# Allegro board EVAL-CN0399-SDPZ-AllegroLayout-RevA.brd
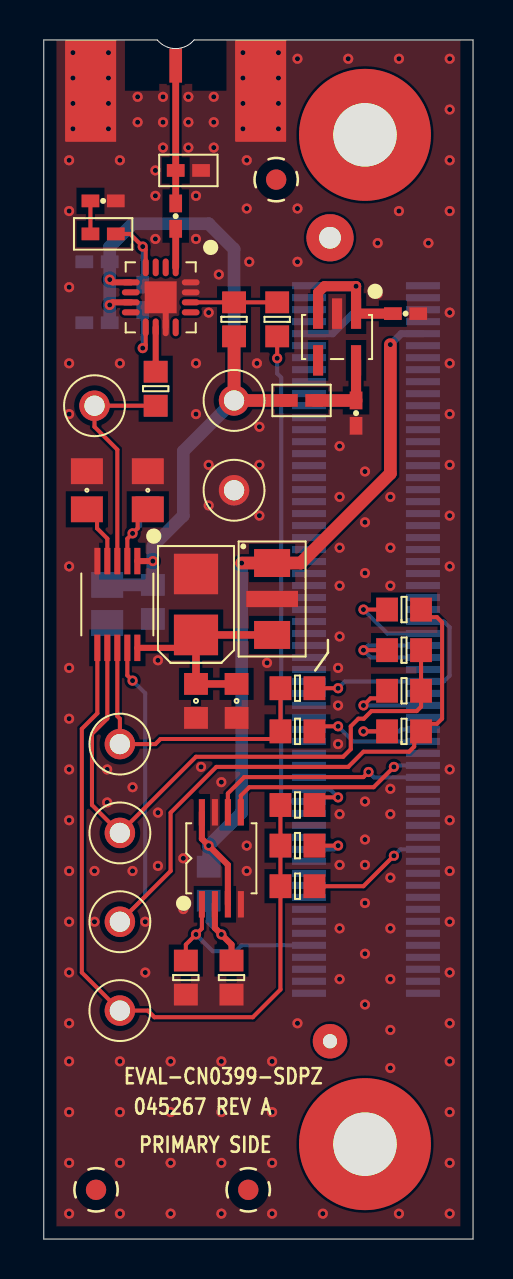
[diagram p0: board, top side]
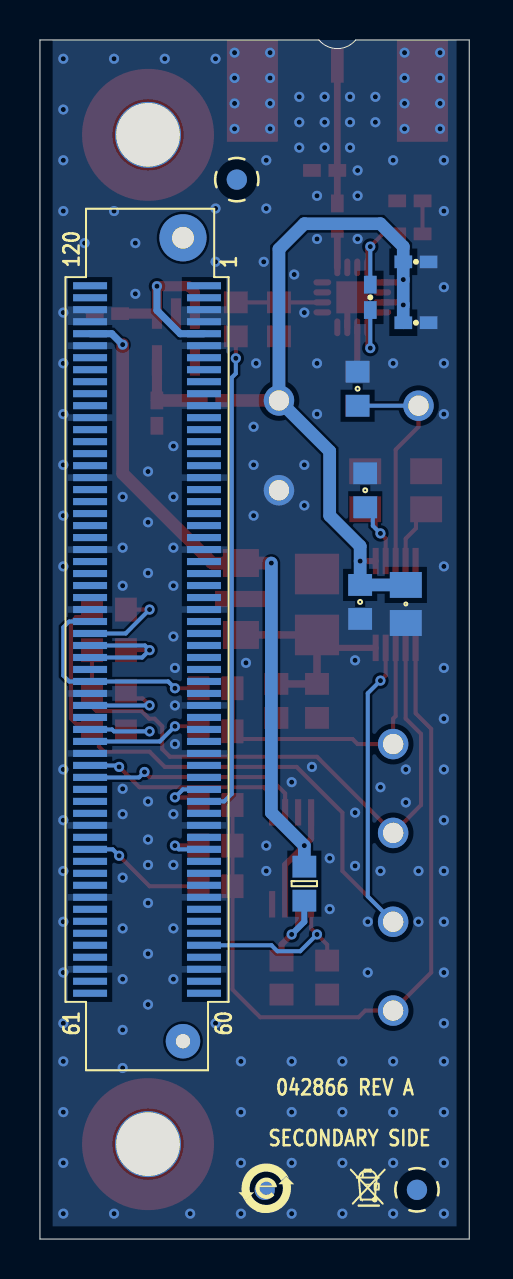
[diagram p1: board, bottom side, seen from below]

Outline 21.49 x 59.99 mm; copper layers: TOP, L2_GND, L3_GND, BOTTOM. Coordinates in mm from the lower left corner of the outline.
Outline path: 5.68,59.99 0,59.99 0,0 21.49,0 21.49,59.99 7.52,59.99

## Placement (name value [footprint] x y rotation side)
C1  1uF  [C0402]  18.11 46.3 0 top
C2  0.1UF  [C0402]  2.97 51.94 0 top
C3  1uF  [C0402]  15.63 41.32 270 top
C4  0.47uF  [C0402]  6.6 51.18 270 top
C5  0.1UF  [C0402]  4.95 47.12 270 bottom
C6  100PF  [C0402]  2.67 48.9 180 bottom
C7  0.1UF  [C0402]  2.67 45.85 180 bottom
C8  TBD0603  [C0603]  5.59 42.55 90 bottom
C10  10uF  [C3528]  7.62 31.75 90 top
C11  1uF  [C0805]  2.16 37.47 90 top
C12  0.1uF  [C0603]  9.65 26.92 270 top
C13  0.1uF  [C0603]  7.62 26.92 270 top
C14  0.1uF  [C0603]  5.21 37.47 90 bottom
C15  1uF  [C0805]  5.21 37.47 90 top
C16  1uF  [C0805]  3.18 31.78 270 bottom
C17  0.1uF  [C0603]  5.46 31.88 270 bottom
CONSTB  5001  [CNKEY5001TP]  3.81 11.43 0 top
CSB  5001  [CNKEY5001TP]  3.81 20.32 0 top
FL1  1000pF  [FLSML126W71H87]  11.43 32.02 270 top
NOREF  -  []  -144.78 23.77 0 top
NOREF#2  -  []  16.08 4.75 0 top
NOREF#3  -  [unnamed#2]  10.24 2.46 0 top
NOREF#4  -  []  6.53 59.57 0 top
NOREF#5  -  []  -166.45 262.33 0 top
NOREF#6  -  []  -263.14 5.03 0 top
NOREF#7  -  []  -188.06 -103.86 0 top
NOREF#8  -  [unnamed#2]  2.62 2.46 0 top
NOREF#9  -  []  6.6 60.76 0 top
NOREF#10  -  []  0 59.99 270 top
NOREF#11  -  []  0 0.05 0 top
NOREF#12  -  [unnamed#2]  11.63 53.01 0 top
NOREF#13  -  []  21.49 0 90 top
NOREF#14  -  []  21.49 59.99 180 top
NOREF#15  -  []  0 59.99 0 top
NOREF#16  -  []  -188.06 -103.86 0 top
NOREF#17  -  []  0 0 0 top
NOREF#18  -  []  -188.91 -27.62 0 top
NOREF#19  -  []  0 0 0 top
NOREF#20  -  []  6.59 59.56 0 top
NOREF#21  -  []  -414.4 -247.14 0 top
NOREF#22  -  []  16.08 4.75 0 top
NOREF#23  -  []  21.49 0 90 top
NOREF#24  -  []  10.16 2.54 180 bottom
NOREF#25  -  [unnamed#2]  11.63 53.01 180 bottom
NOREF#26  -  []  5.03 2.57 180 bottom
NOREF#27  -  [unnamed#2]  2.62 2.46 180 bottom
NOREF#28  -  [unnamed#2]  10.24 2.46 180 bottom
P1  FX8-120S-SV(21)  [CNHRSFX8-120S-SV_A]  16.13 30 270 bottom
R1  0  [R0603]  12.7 19.68 0 top
R2  0  [R0603]  12.7 21.72 0 top
R3  TBD0603  [R0603]  12.7 17.65 180 top
R4  100K  [R0603]  7.11 13.08 270 top
R5  0  [R0603]  12.7 25.4 180 top
R6  0  [R0603]  18.03 25.4 0 top
R7  0  [R0603]  18.03 27.43 0 top
R8  0  [R0603]  12.7 27.56 180 top
R9  0  [R0603]  18.03 29.46 0 top
R10  0  [R0603]  18.03 31.5 0 top
R11  TBD0603  [R0603]  8.26 17.78 270 bottom
R12  100K  [R0603]  9.4 13.08 270 top
R13  4.02  [R0402]  2.97 50.29 180 top
R14  82.5  [R0402]  7.24 53.47 0 top
R15  0  [R0402]  12.9 41.96 180 top
R16  0  [R0603]  11.68 46.02 90 top
R17  0  [R0603]  9.53 46.02 270 top
R18  0  [R0603]  5.6 42.55 270 top
RFIN  142-0801-811  [CNSMAL686W375H161]  6.6 57.63 90 top
SCLK  5001  [CNKEY5001TP]  3.81 24.77 0 top
SDO  5001  [CNKEY5001TP]  3.81 15.88 0 top
TPGND  20-2137  [CNKEY5001TP]  9.53 37.47 0 top
TPVPOS  20-313137  [CNKEY5001TP]  9.53 41.96 0 top
U1  ADL5904ACPZ  [QFN16_3X3_PAD1_6X1_6]  5.85 47.12 180 top
U2  24LC32A-I/MS  [MSOP8]  8.89 19.05 0 top
U3  ADP160AUJZ-3.3  [TSOT-5]  14.68 45.13 180 top
U4  AD7091RBRMZ  [RM10]  3.68 31.75 180 top
VRMS  5001  [CNKEY5001TP]  2.54 41.69 0 top

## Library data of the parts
C1 C3 = CAP: Tolerance: 10; User Part Number: UPN; part number: CAP_SM-1UF,16V,10,E020874,C0402; tolerance: 10
C2 C5 C7 = CAP: Tolerance: 10; User Part Number: UPN; part number: CAP_SM-0.1UF,16V,10,E007200,C0402; tolerance: 10
C4 = CAP: Tolerance: 10; User Part Number: UPN; part number: CAP_SM-0.47UF,16V,10,E016653,C0402; tolerance: 10
C6 = CAP: Tolerance: 5; User Part Number: UPN; part number: CAP_SM-100PF,50V,5,E023843,C0402; tolerance: 5
C8 = CAP: User Part Number: UPN; part number: CAP_SM-TBD0603,TBD0603,TBD0603,E000382,C0603
C10 = CAPP: User Part Number: UPN; Tolerance: 10; part number: CAPP_SM-10UF,20V,10,E011346,C3528; tolerance: 10
C11 C15 C16 = CAP: Tolerance: 10; User Part Number: UPN; part number: CAP_SM-1UF,100V,10,E014208,C0805; tolerance: 10
C12 C13 = CAP: Tolerance: 10; User Part Number: UPN; part number: CAP_SM-0.1UF,50V,10,E015248,C0603; tolerance: 10
C14 C17 = CAP: Tolerance: 10; User Part Number: UPN; part number: CAP_SM-0.1UF,50V,10,E011865,C0603; tolerance: 10
CONSTB CSB SCLK SDO VRMS = CNTP1P: User Part Number: UPN; alternate symbols: (CNBANANA_ALT); part number: CNTP1P_TH-5001,E005347,CNKEY5001TP
FL1 = FLTR3P_V3: User Part Number: UPN; part number: FLTR3P_V3_SM-1000PF,E019686,FLSML126W71H87
P1 = CN120P_V4: User Part Number: UPN; part number: CN120P_V4_SM-FX8-120S-SV(21),E016993,CNHRSFX8-120S-SV_A
R1 R2 R5-R10 R16 R17 = RES: Tolerance: 1; User Part Number: UPN; part number: RES_SM-0,E004207,1/16W,1,R0603; tolerance: 1
R3 R11 = RES: User Part Number: UPN; part number: RES_SM-TBD0603,E004050,TBD0603,TBD0603,R0603
R4 R12 = RES: Tolerance: 1; User Part Number: UPN; part number: RES_SM-100K,E018430,1/16W,1,R0603; tolerance: 1
R13 = RES: Tolerance: 1; User Part Number: UPN; part number: RES_SM-4.02,E016605,1/16W,1,R0402; tolerance: 1
R14 = RES: Tolerance: 1; User Part Number: UPN; part number: RES_SM-82.5,E004031,1/16W,1,R0402; tolerance: 1
R15 = RES: Tolerance: 5; User Part Number: UPN; part number: RES_SM-0,E003438,1/16W,5,R0402; tolerance: 5
R18 = RES: Tolerance: N/A; User Part Number: UPN; part number: RES_SM-0,E005803,N/A,N/A,R0603; tolerance: N/A
RFIN = CNBNC5P: User Part Number: UPN; alternate symbols: (CNAMPHENOL132255-11_ALT); part number: CNBNC5P_SM-142-0801-811,E015296,CNSMAL686W375H161
TPGND = CNTP1P: User Part Number: UPN; alternate symbols: (CNBANANA_ALT); part number: CNTP1P_TH-20-2137,E019484,CNKEY5001TP
TPVPOS = CNTP1P: User Part Number: UPN; alternate symbols: (CNBANANA_ALT); part number: CNTP1P_TH-20-313137,E019485,CNKEY5001TP
U1 = ADL5904: User Part Number: UPN; part number: ADL5904_SM-ADL5904ACPZ,E023038,QFN16_3X3_PAD1_6X1_6
U2 = IC24FC256: User Part Number: UPN; part number: IC24FC256_SM-24LC32A-I/MS,E014160,MSOP8
U3 = ADP160_V2: User Part Number: UPN; part number: ADP160_V2_SM-ADP160AUJZ-3.3,E020094,TSOT-5
U4 = AD7091R_V2: User Part Number: UPN; part number: AD7091R_V2_SM-AD7091RBRMZ,E015495,RM10

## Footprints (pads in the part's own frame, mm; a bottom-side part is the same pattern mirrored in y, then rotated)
C0402
  rect 0.889x0.635 smd: 1(-0.635,0) 2(0.635,0)
C0603
  rect 1.092x1.194 smd: 1(-0.851,0) 2(0.851,0)
C0805
  rect 1.295x1.6 smd: 1(-0.953,0) 2(0.953,0)
C3528
  rect 2.032x2.21 smd: N(1.524,0) P(-1.524,0)
CNHRSFX8-120S-SV_A
  round 6.604 hole 3.175 unplated: (-25.25,0.05) (25.25,0.05)
  round 2.362 hole 1.092 unplated: (-20.1,1.8)
  round 1.727 hole 0.711 unplated: (20.1,1.8)
  rect 0.356x1.702 smd: 1(-17.7,2.851) 2(-17.1,2.851) 3(-16.5,2.851) 4(-15.9,2.851) 5(-15.3,2.851) 6(-14.7,2.851) 7(-14.1,2.851) 8(-13.5,2.851) 9(-12.9,2.851) 10(-12.3,2.851) 11(-11.7,2.851) 12(-11.1,2.851) 13(-10.5,2.851) 14(-9.9,2.851) 15(-9.3,2.851) 16(-8.7,2.851) 17(-8.1,2.851) 18(-7.5,2.851) 19(-6.9,2.851) 20(-6.3,2.851) 21(-5.7,2.851) 22(-5.1,2.851) 23(-4.5,2.851) 24(-3.9,2.851) 25(-3.3,2.851) 26(-2.7,2.851) 27(-2.1,2.851) 28(-1.5,2.851) 29(-0.9,2.851) 30(-0.3,2.851) 31(0.3,2.851) 32(0.9,2.851) 33(1.5,2.851) 34(2.1,2.851) 35(2.7,2.851) 36(3.3,2.851) 37(3.9,2.851) 38(4.5,2.851) 39(5.1,2.851) 40(5.7,2.851) 41(6.3,2.851) 42(6.9,2.851) 43(7.5,2.851) 44(8.1,2.851) 45(8.7,2.851) 46(9.3,2.851) 47(9.9,2.851) 48(10.5,2.851) 49(11.1,2.851) 50(11.7,2.851) 51(12.3,2.851) 52(12.9,2.851) 53(13.5,2.851) 54(14.1,2.851) 55(14.7,2.851) 56(15.3,2.851) 57(15.9,2.851) 58(16.5,2.851) 59(17.1,2.851) 60(17.7,2.851) 61(17.7,-2.851) 62(17.1,-2.851) 63(16.5,-2.851) 64(15.9,-2.851) 65(15.3,-2.851) 66(14.7,-2.851) 67(14.1,-2.851) 68(13.5,-2.851) 69(12.9,-2.851) 70(12.3,-2.851) 71(11.7,-2.851) 72(11.1,-2.851) 73(10.5,-2.851) 74(9.9,-2.851) 75(9.3,-2.851) 76(8.7,-2.851) 77(8.1,-2.851) 78(7.5,-2.851) 79(6.9,-2.851) 80(6.3,-2.851) 81(5.7,-2.851) 82(5.1,-2.851) 83(4.5,-2.851) 84(3.9,-2.851) 85(3.3,-2.851) 86(2.7,-2.851) 87(2.1,-2.851) 88(1.5,-2.851) 89(0.9,-2.851) 90(0.3,-2.851) 91(-0.3,-2.851) 92(-0.9,-2.851) 93(-1.5,-2.851) 94(-2.1,-2.851) 95(-2.7,-2.851) 96(-3.3,-2.851) 97(-3.9,-2.851) 98(-4.5,-2.851) 99(-5.1,-2.851) 100(-5.7,-2.851) 101(-6.3,-2.851) 102(-6.9,-2.851) 103(-7.5,-2.851) 104(-8.1,-2.851) 105(-8.7,-2.851) 106(-9.3,-2.851) 107(-9.9,-2.851) 108(-10.5,-2.851) 109(-11.1,-2.851) 110(-11.7,-2.851) 111(-12.3,-2.851) 112(-12.9,-2.851) 113(-13.5,-2.851) 114(-14.1,-2.851) 115(-14.7,-2.851) 116(-15.3,-2.851) 117(-15.9,-2.851) 118(-16.5,-2.851) 119(-17.1,-2.851) 120(-17.7,-2.851)
CNKEY5001TP
  round 1.524 hole 1.016: 1(0,0)
CNSMAL686W375H161
  rect 1.702x0.635 smd: 1(1.079,0)
  rect 5.08x2.54 smd: 2(-0.178,4.255) 3(-0.178,4.255) 4(-0.178,-4.255) 5(-0.178,-4.255)
FLSML126W71H87
  rect 1.397x1.803 smd: 1(-1.799,0) 3(1.799,0)
  rect 0.813x2.591 smd: 2(0,0)
MSOP8
  rect 0.305x1.321 smd: 1(-0.975,-2.3) 2(-0.325,-2.3) 3(0.325,-2.3) 4(0.975,-2.3) 5(0.975,2.3) 6(0.325,2.3) 7(-0.325,2.3) 8(-0.975,2.3)
QFN16_3X3_PAD1_6X1_6
  oval 0.305x0.889 smd: 1(-0.75,-1.5) 2(-0.25,-1.5) 3(0.25,-1.5) 4(0.75,-1.5) 9(0.75,1.5) 10(0.25,1.5) 11(-0.25,1.5) 12(-0.75,1.5)
  oval 0.889x0.305 smd: 5(1.5,-0.75) 6(1.5,-0.25) 7(1.5,0.25) 8(1.5,0.75) 13(-1.5,0.75) 14(-1.5,0.25) 15(-1.5,-0.25) 16(-1.5,-0.75)
  rect 1.6x1.6 smd: PAD(0,0)
R0402
  rect 0.889x0.635 smd: 1(-0.635,0) 2(0.635,0)
R0603
  rect 1.092x1.194 smd: 1(-0.851,0) 2(0.851,0)
RM10
  rect 0.305x1.321 smd: 1(-1,-2.171) 2(-0.5,-2.171) 3(0,-2.171) 4(0.5,-2.171) 5(1,-2.171) 6(1,2.171) 7(0.5,2.171) 8(0,2.171) 9(-0.5,2.171) 10(-1,2.171)
TSOT-5
  rect 0.508x1.524 smd: 1(-0.95,-1.17) 2(0,-1.17) 3(0.95,-1.17) 4(0.95,1.17) 5(-0.95,1.17)
unnamed#2
  round 1.016 smd: (0,0)

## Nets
5VUSB: C1.1(N1) P1.5(USB_VBUS) U3.1(VIN) U3.3(EN)
AGND: C1.2(N2) C2.2(N2) C3.2(N2) C6.2(N2) C7.2(N2) C8.2(N2) C10.N(N2) C11.2(N2) C12.2(N2) C13.2(N2) C14.2(N2) C15.2(N2) C16.2(N2) C17.2(N2) FL1.2(C) P1.3(GND1) P1.4(GND2) P1.6(GND3) P1.11(GND4) P1.17(GND5) P1.23(GND6) P1.28(GND7) P1.36(GND8) P1.40(GND9) P1.46(GND10) P1.52(GND11) P1.58(GND12) P1.63(GND13) P1.69(GND14) P1.75(GND15) P1.81(GND16) P1.86(GND17) P1.93(GND18) P1.98(GND19) P1.104(GND20) P1.109(GND21) P1.115(GND22) P1.117(GND23) P1.118(GND24) R4.2(N2) R12.2(N2) R14.2(N2) RFIN.2(SH1) RFIN.3(SH2) RFIN.4(SH3) RFIN.5(SH4) TPGND.1(N1) U1.11(GND) U1.15(RST) U1.16(V-) U1.PAD(EPAD) U2.4(VSS) U2.7(WP) U3.2(GND) U4.5(GND)
CONVSTB: CONSTB.1(N1) R1.1(N1) R2.1(N1) R3.2(N2) U4.6(CONVST_N)
CSB: CSB.1(N1) R7.2(N2) R9.2(N2) U4.7(CS_N)
GPIO2: P1.44(GPIO2) R16.1(N1)
RFIN: C4.1(N1) R14.1(N1) RFIN.1(CNTR)
SCLK: R5.2(N2) R8.2(N2) SCLK.1(N1) U4.8(SCLK)
SDO: R6.2(N2) R10.2(N2) SDO.1(N1) U4.9(SDO)
UNNAMED_2_AD7091RV2_I40_REFOUT: C14.1(N1) C15.1(N1) U4.2(REFOUT)
UNNAMED_2_AD7091RV2_I40_REGCAP: C11.1(N1) U4.4(REGCAP)
UNNAMED_2_AD7091RV2_I40_VDRIVE: C10.P(N1) C12.1(N1) C13.1(N1) FL1.3(L2) U4.10(VDRIVE)
UNNAMED_2_ADL5904_I16_CRMS: C5.2(N2) U1.9(CRMS)
UNNAMED_2_ADL5904_I16_DECL: C5.1(N1) R13.1(N1) U1.4(DECL)
UNNAMED_2_ADL5904_I16_ENBL: R16.2(N2) R17.1(N1) U1.14(ENBL)
UNNAMED_2_ADL5904_I16_RFIN: C4.2(N2) U1.1(RFIN)
UNNAMED_2_ADL5904_I16_VRMS: R18.1(N1) U1.10(VRMS)
UNNAMED_2_ADP160V2_I58_VOUT: C3.1(N1) R15.1(N1) U3.5(VOUT)
UNNAMED_2_CAP_I7_N1: C2.1(N1) R13.2(N2)
UNNAMED_3_CN120PV4_I25_EEPROMA0: P1.56(EEPROM_A0) R4.1(N1) U2.1(A0)
UNNAMED_3_CN120PV4_I25_GPIO0: P1.43(GPIO0) R2.2(N2)
UNNAMED_3_CN120PV4_I25_SCL0: P1.79(SCL_0) U2.6(SCL)
UNNAMED_3_CN120PV4_I25_SDA0: P1.80(SDA_0) U2.5(SDA)
UNNAMED_3_CN120PV4_I25_SPICLK: P1.82(SPI_CLK) R5.1(N1)
UNNAMED_3_CN120PV4_I25_SPIMISO: P1.83(SPI_MISO) R6.1(N1)
UNNAMED_3_CN120PV4_I25_SPISELA: P1.85(SPI_SEL_A) R7.1(N1)
UNNAMED_3_CN120PV4_I25_SPORTDR0: P1.91(SPORT_DR0) R10.1(N1)
UNNAMED_3_CN120PV4_I25_SPORTRFS: P1.89(SPORT_TFS) P1.90(SPORT_RFS) R9.1(N1)
UNNAMED_3_CN120PV4_I25_SPORTRSC: P1.87(SPORT_TSCLK) P1.92(SPORT_RSCLK) R8.1(N1)
UNNAMED_3_CN120PV4_I25_TMRA: P1.48(TMR_A) R1.2(N2)
UNNAMED_3_CN120PV4_I25_TMRB: P1.73(TMR_B) R3.1(N1)
UNNAMED_3_IC24FC256_I20_A1: R11.2(N2) R12.1(N1) U2.2(A1)
VIO_CONNECTOR: FL1.1(L1) P1.116(VIO(+3.3V)) R11.1(N1) U2.3(A2) U2.8(VCC)
VPOS: C6.1(N1) C7.1(N1) C16.1(N1) C17.1(N1) R15.2(N2) R17.2(N2) TPVPOS.1(N1) U1.5(VPOS1) U1.7(DNC3) U4.1(VDD)
VRMS: C8.1(N1) R18.2(N2) U4.3(VIN) VRMS.1(N1)

Pads without a net: P1 1 2 7 8 9 10 12 13 14 15 16 18 19 20 21 22 24 25 26 27 29 30 31 32 33 34 35 37 38 39 41 42 45 47 49 50 51 53 54 55 57 59 60 61 62 64 65 66 67 68 70 71 72 74 76 77 78 84 88 94 95 96 97 99 100 101 102 103 105 106 107 108 110 111 112 113 114 119 120; U1 2 3 6 8 12 13; U3 4

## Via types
v1: diameter 0.508, hole 0.254, TOP to BOTTOM, 187 vias

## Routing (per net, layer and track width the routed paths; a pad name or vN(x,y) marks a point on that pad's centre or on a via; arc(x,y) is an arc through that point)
5VUSB: length 10.3
  TOP w0.508: C1.1 U3.1 v1(15.63,47.67) 14.05,47.67 13.73,47.36 U3.3
  BOTTOM w0.356: v1(15.63,47.67) 15.63,46.46 14.46,45.3 P1.5
AGND: length 1.6
  TOP w0.305: U1.11 6.1,46.87 U1.PAD
  vias: v1(1.27,53.98) v1(1.27,51.44) v1(1.27,47.62) v1(1.27,43.82) v1(1.27,41.28) v1(1.27,33.66) v1(1.27,28.57) v1(1.27,26.04) v1(1.27,23.49) v1(1.27,20.95) v1(1.27,18.41) v1(1.27,15.88) v1(1.27,13.34) v1(1.27,10.79) v1(1.27,8.89) v1(1.27,6.35) v1(1.27,3.81) v1(1.27,1.27) v1(1.46,59.36) v1(1.46,58.09) v1(1.46,56.82) v1(1.46,55.55) v1(2.54,18.41) v1(2.54,15.88) v1(3.18,23.49) v1(3.18,21.84) v1(3.24,59.36) v1(3.24,58.09) v1(3.24,56.82) v1(3.24,55.55) v1(3.81,53.98) v1(3.81,43.82) v1(3.81,8.89) v1(3.81,6.35) v1(3.81,3.81) v1(3.81,1.27) v1(4.45,22.61) v1(4.45,18.41) v1(4.7,57.15) v1(4.7,55.88) v1(5.08,15.88) v1(5.08,13.34) v1(5.59,53.47) v1(5.59,52.2) v1(5.59,50.04) v1(5.71,28.96) v1(5.71,21.34) v1(5.71,18.67) v1(5.97,57.15) v1(5.97,55.88) v1(5.97,54.61) v1(6.35,8.89) v1(6.35,6.35) v1(6.35,3.81) v1(6.35,1.27) v1(6.99,19.05) v1(6.99,16.51) v1(7.24,57.15) v1(7.24,55.88) v1(7.24,54.61) v1(7.62,52.2) v1(7.62,50.04) v1(7.62,43.82) v1(7.62,41.28) v1(7.87,23.62) v1(8.26,46.36) v1(8.26,38.73) v1(8.26,36.7) v1(8.51,57.15) v1(8.51,55.88) v1(8.51,54.61) v1(8.76,48.26) v1(8.89,22.86) v1(8.89,8.89) v1(8.89,6.35) v1(8.89,3.81) v1(8.89,1.27) v1(9.97,59.36) v1(9.97,58.09) v1(9.97,56.82) v1(9.97,55.55) v1(10.16,53.98) v1(10.16,51.56) v1(10.16,19.68) v1(10.16,18.41) v1(10.29,48.9) v1(10.67,43.82) v1(10.8,40.64) v1(10.8,38.73) v1(10.8,36.2) v1(11.18,28.83) v1(11.43,8.89) v1(11.43,6.35) v1(11.43,3.81) v1(11.43,1.27) v1(11.75,59.36) v1(11.75,58.09) v1(11.75,56.82) v1(11.75,55.55) v1(12.7,59.05) v1(12.7,51.56) v1(12.7,48.9) v1(12.7,10.79) v1(13.97,1.27) v1(14.81,39.67) v1(14.81,37.13) v1(14.81,34.59) v1(14.81,32.69) v1(14.81,30.15) v1(14.73,28.57) v1(14.73,26.7) v1(14.73,24.77) v1(14.81,21.26) v1(14.81,18.72) v1(14.81,15.54) v1(14.81,13) v1(15.24,59.05) v1(16.08,38.4) v1(16.08,35.86) v1(16.08,33.32) v1(16.08,21.89) v1(16.08,19.99) v1(16.08,18.72) v1(16.08,16.81) v1(16.08,14.27) v1(16.08,11.73) v1(16.71,49.83) v1(16.71,47.29) v1(17.35,37.13) v1(17.35,34.59) v1(17.35,32.69) v1(17.35,22.53) v1(17.35,21.26) v1(17.35,18.08) v1(17.35,15.54) v1(17.35,13) v1(17.35,10.46) v1(17.35,8.56) v1(17.78,59.05) v1(17.78,51.44) v1(17.78,1.27) v1(19.25,49.83) v1(20.32,59.05) v1(20.32,56.52) v1(20.32,53.98) v1(20.32,51.44) v1(20.32,46.36) v1(20.32,43.82) v1(20.32,41.28) v1(20.32,38.73) v1(20.32,36.2) v1(20.32,33.66) v1(20.32,23.49) v1(20.32,20.95) v1(20.32,18.41) v1(20.32,15.88) v1(20.32,13.34) v1(20.32,10.79) v1(20.32,8.89) v1(20.32,6.35) v1(20.32,3.81) v1(20.32,1.27)
CONVSTB: length 37.2
  TOP w0.203: R2.1 R1.1 R3.2 11.85,12.48 10.46,11.1 5.54,11.1 5.21,11.43 CONSTB.1 1.91,13.34 1.91,25.53 2.68,26.31 U4.6
CSB: length 31.3
  TOP w0.203: R9.2 R7.2 18.88,26.63 18.67,26.42 16.4,26.42 16.02,26.04 15.75,26.04 15.37,25.65 15.37,24.51 14.99,24.13 7.62,24.13 CSB.1 2.41,21.72 2.41,25.27 3.18,26.04 U4.7
GPIO2: length 24.5
  TOP w0.203: R16.1 v1(11.68,44.07)
  BOTTOM w0.203: P1.44 12.27,21.9 11.89,22.28 11.89,43.1 11.68,43.31 v1(11.68,44.07)
RFIN: length 6.9
  TOP w0.343: C4.1 R14.1 RFIN.1
SCLK: length 15.3
  TOP w0.203: R8.2 R5.2 11.47,25.02 5.84,25.02 5.59,24.77 SCLK.1 3.81,26.04 3.68,26.16 U4.8
SDO: length 43
  TOP w0.203: SDO.1 6.35,18.41 6.35,21.34 8.64,23.62 15.24,23.62 16,24.38 18.29,24.38 18.54,24.64 18.54,25.06 R6.2 19.27,25.78 19.69,25.78 19.94,26.04 19.94,30.86 19.69,31.11 19.27,31.11 R10.2 ; U4.9 4.18,28.2 v1(4.45,27.94)
  BOTTOM w0.203: v1(4.45,27.94) 5.08,27.3 5.08,17.14 SDO.1
UNNAMED_2_AD7091RV2_I40_REFOUT: length 4.6
  TOP w0.203: C15.1 4.7,36 4.7,35.56 v1(4.45,35.31) 4.18,35.04 U4.2
  BOTTOM w0.203: v1(4.45,35.31) 4.83,35.69 4.83,36.23 C14.1
UNNAMED_2_AD7091RV2_I40_REGCAP: length 3
  TOP w0.203: C11.1 2.67,36 2.67,35.56 3.18,35.04 U4.4
UNNAMED_2_AD7091RV2_I40_VDRIVE: length 11.5
  TOP w0.305: C10.P 6.97,29.58 U4.10
  TOP w0.381: C12.1 C13.1 C10.P FL1.3
UNNAMED_2_ADL5904_I16_CRMS: length 3
  TOP w0.203: U1.9 5.1,44.73 v1(4.95,44.58)
  BOTTOM w0.203: C5.2 v1(4.95,44.58)
UNNAMED_2_ADL5904_I16_DECL: length 4.6
  TOP w0.203: R13.1 4.32,50.29 v1(4.95,49.66) 5.1,49.51 U1.4
  BOTTOM w0.203: C5.1 v1(4.95,49.66)
UNNAMED_2_ADL5904_I16_ENBL: length 4.3
  TOP w0.203: R16.2 R17.1 U1.14
UNNAMED_2_ADL5904_I16_RFIN: length 1.9
  TOP w0.343: U1.1 C4.2
UNNAMED_2_ADL5904_I16_VRMS: length 2.2
  TOP w0.305: U1.10 R18.1
UNNAMED_2_ADP160V2_I58_VOUT: length 4.1
  TOP w0.508: U3.5 C3.1
  TOP w0.635: R15.1 C3.1
UNNAMED_2_CAP_I7_N1: length 1.7
  TOP w0.203: C2.1 R13.2
UNNAMED_3_CN120PV4_I25_EEPROMA0: length 9.3
  TOP w0.203: U2.1 7.91,15.53 v1(7.62,15.24) 7.11,14.73 R4.1
  BOTTOM w0.203: P1.56 9.9,14.7 9.6,14.4 8.46,14.4 v1(7.62,15.24)
UNNAMED_3_CN120PV4_I25_GPIO0: length 3
  TOP w0.203: R2.2 13.93,22.1 v1(14.73,22.1)
  BOTTOM w0.203: P1.43 14.33,22.5 v1(14.73,22.1)
UNNAMED_3_CN120PV4_I25_SCL0: length 11.3
  TOP w0.203: U2.6 9.22,22.3 10.03,23.11 16,23.11 v1(16.26,23.37)
  BOTTOM w0.203: P1.79 16.53,23.1 v1(16.26,23.37)
UNNAMED_3_CN120PV4_I25_SDA0: length 10.6
  TOP w0.203: v1(17.53,23.62) 16.51,22.61 10.29,22.61 9.87,22.18 U2.5
  BOTTOM w0.203: P1.80 17.6,23.7 v1(17.53,23.62)
UNNAMED_3_CN120PV4_I25_SPICLK: length 5.8
  TOP w0.203: v1(14.73,25.65) 13.8,25.65 R5.1
  BOTTOM w0.203: P1.82 15.49,24.9 v1(14.73,25.65)
UNNAMED_3_CN120PV4_I25_SPIMISO: length 4.2
  TOP w0.203: R6.1 v1(16,25.4)
  BOTTOM w0.203: P1.83 17.88,25.5 17.78,25.4 v1(16,25.4)
UNNAMED_3_CN120PV4_I25_SPISELA: length 4.5
  TOP w0.203: v1(16,26.7) 16.36,27.05 16.8,27.05 R7.1
  BOTTOM w0.203: P1.85 v1(16,26.7)
UNNAMED_3_CN120PV4_I25_SPORTDR0: length 4.7
  TOP w0.203: R10.1 v1(16,31.5)
  BOTTOM w0.203: v1(16,31.5) 17.2,30.3 P1.91
UNNAMED_3_CN120PV4_I25_SPORTRFS: length 7.4
  TOP w0.203: R9.1 v1(16,29.46)
  BOTTOM w0.203: P1.89 16.37,29.1 v1(16,29.46) 16.24,29.7 P1.90
UNNAMED_3_CN120PV4_I25_SPORTRSC: length 10.9
  TOP w0.203: R8.1 v1(14.73,27.56)
  BOTTOM w0.203: v1(14.73,27.56) 15.07,27.9 P1.87 20.02,27.9 20.32,28.19 20.32,30.61 20.03,30.9 P1.92
UNNAMED_3_CN120PV4_I25_TMRA: length 2.7
  TOP w0.203: R1.2 v1(14.73,19.68)
  BOTTOM w0.203: P1.48 14.54,19.5 v1(14.73,19.68)
UNNAMED_3_CN120PV4_I25_TMRB: length 6.2
  TOP w0.203: v1(17.53,19.18) 16,17.65 R3.1
  BOTTOM w0.203: v1(17.53,19.18) 17.85,19.5 P1.73
UNNAMED_3_IC24FC256_I20_A1: length 5.1
  TOP w0.305: R12.1 9.4,14.73 v1(8.89,15.24) 8.56,15.57 U2.2
  BOTTOM w0.305: R11.2 8.26,15.88 v1(8.89,15.24)
VIO_CONNECTOR: length 38.6
  TOP w0.305: U2.3 9.22,18.72 v1(8.26,19.68) 7.91,20.03 U2.8
  TOP w0.635: v1(17.35,44.75) 17.35,38.3 12.87,33.82 FL1.1 v1(9.91,33.82)
  BOTTOM w0.356: P1.116 17.89,45.3 v1(17.35,44.75)
  BOTTOM w0.635: R11.1 v1(8.26,19.68) 9.91,21.34 v1(9.91,33.82)
VPOS: length 40.7
  TOP w0.305: U1.7 3.43,46.87 v1(3.3,46.74) ; U1.5 3.44,47.87 v1(3.3,48.01) ; U4.1 v1(5.46,33.92)
  TOP w0.635: R17.2 TPVPOS.1 R15.2
  BOTTOM w0.635: C16.1 C17.1 v1(5.46,33.92) 5.46,34.67 6.99,36.19 6.99,39.42 TPVPOS.1 9.53,49.53 8.26,50.8 4.45,50.8 3.3,49.66 C6.1 v1(3.3,48.01) v1(3.3,46.74) C7.1
VRMS: length 14.4
  TOP w0.203: U4.3 3.68,39.5 2.54,40.64 VRMS.1 R18.2
  BOTTOM w0.203: C8.1 VRMS.1

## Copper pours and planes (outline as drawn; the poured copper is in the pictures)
AGND on TOP: 0.63,0.63 0.63,59.99 20.85,59.99 20.85,0.63 ; 1 cut-out
AGND on BOTTOM: 0.63,0.63 0.63,59.99 20.85,59.99 20.85,0.63
AGND on L2_GND, L3_GND: 0.63,0.63 0.63,59.36 20.85,59.36 20.85,0.63

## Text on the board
Ref Des/Silkscreen Bottom: SECONDARY SIDE | 042866 REV A
Ref Des/Silkscreen Top: 045267 REV A | PRIMARY SIDE | EVAL-CN0399-SDPZ
PAGE_OUTLINE: CFTL BOARD
DIMENSION: SEE NOTE 15
User.14: 15.    VIAS FILLED WITH NON-CONDUCTIVE EPOXY GROUND FLUSH AND PLATED OVER. | 16.    EXPOSED COPPER ON BOARD EDGE CAN NOT BE PULLED BACK. | SURFACE FINISH; | SURFACE TO BE HARD GOLD PLATE IN PRIMARY AND | SECONDARY PROCESS PER MIL-G-45204B, CLASS I, | GRADE C, TYPE I. PRIMARY GOLD TO BE 05-15 MICRO | INCHES MAXIMUM OVER LOW STRESS NICKEL PLATING | 200 MICRO INCHES MINIMUM PER QQ-N-290, CLASS I | REPLATE SECONDARY PROCESS WITH 30 MICRO INCHES | MINIMUM ON SELECTIVE AREA PROVIDED. | PRIMARY SIDE    (LAYER 1, 50 OHM CONTROLLED IMPEDANCE) | 0.010"
User.16: L2 GROUND | 08-      -07
User.17: L3 POWER | 08-      -08
User.24: K. BARRETT | 04/07/16 | K.BARRETT | PRIMARY SIDE | 24355 | CFTL BOARD
User.25: 24355
User.26: 2 | SEE NOTE 15 | MAX DIA THRU | LAYER 1 TO LAYER 2 | FABRICATION | 09 | C
User.36: REWORK | 13-
User.37: FIGURE | SIZE | 10.0 | 40.0 | 28.0 | 43.0 | 125.0 | PLATED | NON-PLATED | FINISHED HOLES IN MILS | ALL UNITS ARE IN MILS | QTY | 187 | 7 | 1 | 2 | TOLERANCE/NOTES
